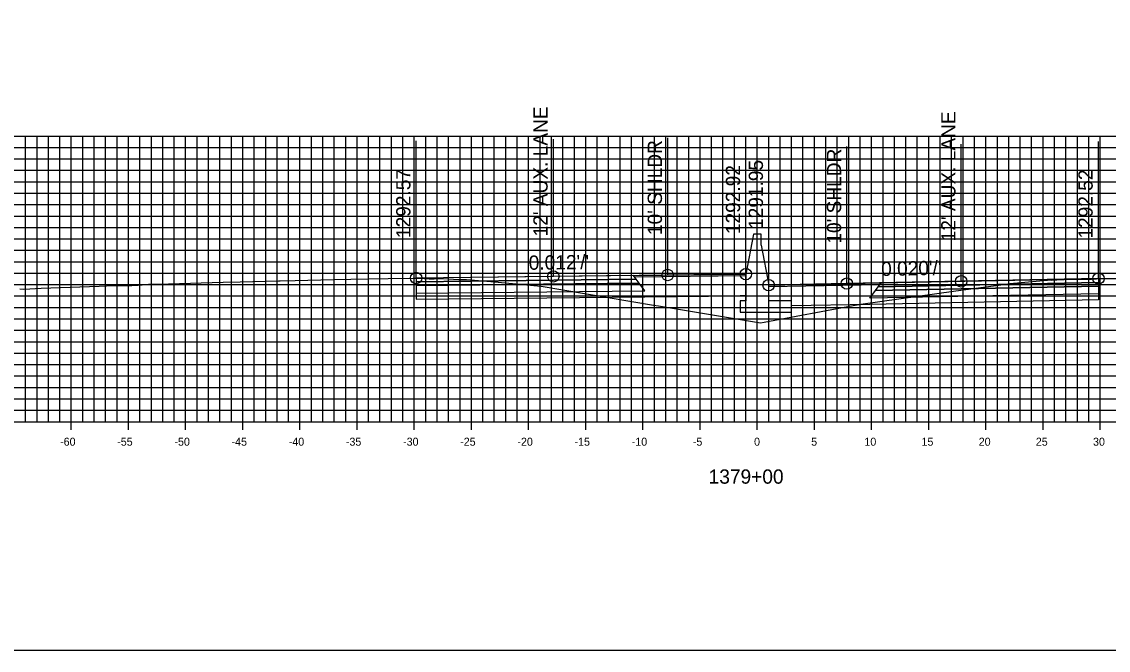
# Model space of a CAD drawing. Extents: x 674939 to 678919, y 750652 to 765176.
# Drawn here: x 678674.2 to 678769.2, y 755062.6 to 755117.6 of the extents above; entities that cross this region are included whole.
import ezdxf

# ---------------------------------------------------------------- set-up
doc = ezdxf.new("R2010")
doc.units = 0
for name, color, linetype in [('Level 10', 7, 'Continuous'), ('Level 17', 7, 'Continuous'), ('Level 18', 7, 'Continuous'), ('Level 19', 7, 'Continuous'), ('Level 20', 7, 'Continuous'), ('Level 22', 7, 'Continuous'), ('Level 23', 7, 'Continuous'), ('Level 4', 7, 'Continuous'), ('Level 8', 7, 'Continuous'), ('Level 9', 7, 'Continuous')]:
    doc.layers.add(name, color=color, linetype=linetype)

msp = doc.modelspace()

# ---------------------------------------------------------------- linework, layer by layer
at = {"layer": 'Level 10'}
msp.add_lwpolyline([(678674.042, 755094.176), (678674.332, 755094.156), (678674.913, 755094.185), (678675.9, 755094.228), (678680.981, 755094.416), (678682.242, 755094.463), (678683.839, 755094.479), (678684.388, 755094.492), (678685.071, 755094.555), (678685.277, 755094.571), (678685.32, 755094.575), (678685.387, 755094.58), (678687.032, 755094.629), (678691.823, 755094.767), (678693.303, 755094.803), (678696.642, 755094.871), (678696.807, 755094.878), (678698.114, 755094.919), (678701.455, 755094.984), (678704.511, 755095.042), (678706.253, 755095.078), (678708.433, 755095.11), (678708.698, 755095.122), (678708.723, 755095.124), (678708.733, 755095.124), (678708.952, 755095.107), (678709.824, 755095.066), (678710.261, 755095.06), (678710.988, 755095.069), (678712.441, 755095.007), (678712.934, 755094.987), (678712.972, 755094.992), (678713.088, 755095.009), (678715.225, 755094.813), (678719.621, 755094.414), (678729.443, 755092.761), (678729.89, 755092.688), (678732.508, 755092.249), (678738.826, 755091.191), (678739.145, 755091.247), (678746.926, 755092.731), (678747.79, 755092.861), (678755.694, 755093.961), (678760.289, 755094.601), (678760.626, 755094.632), (678764.228, 755094.97), (678764.277, 755094.957), (678764.307, 755094.946), (678764.746, 755094.956), (678766.015, 755095.011), (678766.893, 755095.028), (678767.781, 755095.037), (678768.199, 755095.065), (678768.372, 755095.075), (678768.588, 755095.088), (678768.707, 755095.095), (678769.952, 755095.095)], dxfattribs=at)
at = {"layer": 'Level 17'}
for points in [[(678738.203, 755098.967), (678737.533, 755095.467)], [(678738.863, 755097.998), (678738.863, 755098.967), (678738.203, 755098.967), (678738.203, 755098.967)], [(678738.863, 755097.998), (678739.533, 755094.498)], [(678737.533, 755095.467), (678737.533, 755093.123), (678737.033, 755093.123), (678737.033, 755092.123), (678741.533, 755092.123), (678741.533, 755093.123), (678739.533, 755093.123), (678739.533, 755094.498)]]:
    msp.add_lwpolyline(points, dxfattribs=at)
at = {"layer": 'Level 18'}
for points in [[(678737.533, 755095.467), (678730.698, 755095.385), (678720.698, 755095.266), (678708.698, 755095.122)], [(678768.372, 755095.075), (678756.372, 755094.835), (678746.372, 755094.635), (678739.533, 755094.498)]]:
    msp.add_lwpolyline(points, dxfattribs=at)
for points in [[(678708.698, 755095.122), (678708.698, 755094.792), (678727.948, 755095.014), (678727.698, 755095.349)], [(678727.698, 755095.349), (678737.533, 755095.467), (678737.537, 755095.309), (678727.817, 755095.189)], [(678749.253, 755094.535), (678739.533, 755094.341), (678739.533, 755094.498), (678749.372, 755094.695)], [(678768.372, 755095.075), (678768.372, 755094.745), (678749.122, 755094.36), (678749.372, 755094.695)]]:
    msp.add_lwpolyline(points, close=True, dxfattribs=at)
at = {"layer": 'Level 19'}
for points in [[(678708.698, 755094.792), (678708.698, 755094.462), (678728.198, 755094.679), (678727.948, 755095.014)], [(678708.698, 755094.462), (678708.698, 755093.802), (678728.698, 755094.009), (678728.198, 755094.679)], [(678768.372, 755094.415), (678768.372, 755093.755), (678748.372, 755093.355), (678748.872, 755094.025)], [(678768.372, 755094.745), (678768.372, 755094.415), (678748.872, 755094.025), (678749.122, 755094.36)]]:
    msp.add_lwpolyline(points, close=True, dxfattribs=at)
for points in [[(678708.698, 755093.802), (678708.698, 755093.262), (678728.698, 755093.469), (678737.033, 755093.556)], [(678737.534, 755093.561), (678737.033, 755093.556)], [(678768.372, 755093.755), (678768.372, 755093.215), (678748.372, 755092.815), (678741.533, 755092.678)]]:
    msp.add_lwpolyline(points, dxfattribs=at)
at = {"layer": 'Level 20'}
for p, q in [((678638.533, 755107.551), (678838.533, 755107.551)), ((678674.533, 755082.551), (678674.533, 755107.551)), ((678675.533, 755082.551), (678675.533, 755107.551)), ((678676.533, 755082.551), (678676.533, 755107.551)), ((678677.533, 755082.551), (678677.533, 755107.551)), ((678678.533, 755082.551), (678678.533, 755107.551)), ((678679.533, 755082.551), (678679.533, 755107.551)), ((678680.533, 755082.551), (678680.533, 755107.551)), ((678681.533, 755082.551), (678681.533, 755107.551)), ((678682.533, 755082.551), (678682.533, 755107.551)), ((678683.533, 755082.551), (678683.533, 755107.551)), ((678684.533, 755082.551), (678684.533, 755107.551)), ((678685.533, 755082.551), (678685.533, 755107.551)), ((678686.533, 755082.551), (678686.533, 755107.551)), ((678687.533, 755082.551), (678687.533, 755107.551)), ((678688.533, 755082.551), (678688.533, 755107.551)), ((678689.533, 755082.551), (678689.533, 755107.551)), ((678690.533, 755082.551), (678690.533, 755107.551)), ((678691.533, 755082.551), (678691.533, 755107.551)), ((678692.533, 755082.551), (678692.533, 755107.551)), ((678693.533, 755082.551), (678693.533, 755107.551)), ((678694.533, 755082.551), (678694.533, 755107.551)), ((678695.533, 755082.551), (678695.533, 755107.551)), ((678696.533, 755082.551), (678696.533, 755107.551)), ((678697.533, 755082.551), (678697.533, 755107.551)), ((678698.533, 755082.551), (678698.533, 755107.551)), ((678699.533, 755082.551), (678699.533, 755107.551)), ((678700.533, 755082.551), (678700.533, 755107.551)), ((678701.533, 755082.551), (678701.533, 755107.551)), ((678702.533, 755082.551), (678702.533, 755107.551)), ((678703.533, 755082.551), (678703.533, 755107.551)), ((678704.533, 755082.551), (678704.533, 755107.551)), ((678705.533, 755082.551), (678705.533, 755107.551)), ((678706.533, 755082.551), (678706.533, 755107.551)), ((678707.533, 755082.551), (678707.533, 755107.551)), ((678708.533, 755082.551), (678708.533, 755107.551)), ((678709.533, 755082.551), (678709.533, 755107.551)), ((678710.533, 755082.551), (678710.533, 755107.551)), ((678711.533, 755082.551), (678711.533, 755107.551)), ((678712.533, 755082.551), (678712.533, 755107.551)), ((678713.533, 755082.551), (678713.533, 755107.551)), ((678714.533, 755082.551), (678714.533, 755107.551)), ((678715.533, 755082.551), (678715.533, 755107.551)), ((678716.533, 755082.551), (678716.533, 755107.551)), ((678717.533, 755082.551), (678717.533, 755107.551)), ((678718.533, 755082.551), (678718.533, 755107.551)), ((678719.533, 755082.551), (678719.533, 755107.551)), ((678720.533, 755082.551), (678720.533, 755107.551)), ((678721.533, 755082.551), (678721.533, 755107.551)), ((678722.533, 755082.551), (678722.533, 755107.551)), ((678723.533, 755082.551), (678723.533, 755107.551)), ((678724.533, 755082.551), (678724.533, 755107.551)), ((678725.533, 755082.551), (678725.533, 755107.551)), ((678726.533, 755082.551), (678726.533, 755107.551)), ((678727.533, 755082.551), (678727.533, 755107.551)), ((678728.533, 755082.551), (678728.533, 755107.551)), ((678729.533, 755082.551), (678729.533, 755107.551)), ((678730.533, 755082.551), (678730.533, 755107.551)), ((678731.533, 755082.551), (678731.533, 755107.551)), ((678732.533, 755082.551), (678732.533, 755107.551)), ((678733.533, 755082.551), (678733.533, 755107.551)), ((678734.533, 755082.551), (678734.533, 755107.551)), ((678735.533, 755082.551), (678735.533, 755107.551)), ((678736.533, 755082.551), (678736.533, 755107.551)), ((678737.533, 755082.551), (678737.533, 755107.551)), ((678738.533, 755082.551), (678738.533, 755107.551)), ((678739.533, 755082.551), (678739.533, 755107.551)), ((678740.533, 755082.551), (678740.533, 755107.551)), ((678741.533, 755082.551), (678741.533, 755107.551)), ((678742.533, 755082.551), (678742.533, 755107.551)), ((678743.533, 755082.551), (678743.533, 755107.551)), ((678744.533, 755082.551), (678744.533, 755107.551)), ((678745.533, 755082.551), (678745.533, 755107.551)), ((678746.533, 755082.551), (678746.533, 755107.551)), ((678747.533, 755082.551), (678747.533, 755107.551)), ((678748.533, 755082.551), (678748.533, 755107.551)), ((678749.533, 755082.551), (678749.533, 755107.551)), ((678750.533, 755082.551), (678750.533, 755107.551)), ((678751.533, 755082.551), (678751.533, 755107.551)), ((678752.533, 755082.551), (678752.533, 755107.551)), ((678753.533, 755082.551), (678753.533, 755107.551)), ((678754.533, 755082.551), (678754.533, 755107.551)), ((678755.533, 755082.551), (678755.533, 755107.551)), ((678756.533, 755082.551), (678756.533, 755107.551)), ((678757.533, 755082.551), (678757.533, 755107.551)), ((678758.533, 755082.551), (678758.533, 755107.551)), ((678759.533, 755082.551), (678759.533, 755107.551)), ((678760.533, 755082.551), (678760.533, 755107.551)), ((678761.533, 755082.551), (678761.533, 755107.551)), ((678762.533, 755082.551), (678762.533, 755107.551)), ((678763.533, 755082.551), (678763.533, 755107.551)), ((678764.533, 755082.551), (678764.533, 755107.551)), ((678765.533, 755082.551), (678765.533, 755107.551)), ((678766.533, 755082.551), (678766.533, 755107.551)), ((678767.533, 755082.551), (678767.533, 755107.551)), ((678768.533, 755082.551), (678768.533, 755107.551)), ((678638.533, 755106.551), (678838.533, 755106.551)), ((678638.533, 755105.551), (678838.533, 755105.551)), ((678638.533, 755104.551), (678838.533, 755104.551)), ((678638.533, 755103.551), (678838.533, 755103.551)), ((678638.533, 755102.551), (678838.533, 755102.551)), ((678638.533, 755101.551), (678838.533, 755101.551)), ((678638.533, 755100.551), (678838.533, 755100.551)), ((678638.533, 755099.551), (678838.533, 755099.551)), ((678638.533, 755098.551), (678838.533, 755098.551)), ((678638.533, 755097.551), (678838.533, 755097.551)), ((678638.533, 755096.551), (678838.533, 755096.551)), ((678638.533, 755095.551), (678838.533, 755095.551)), ((678638.533, 755094.551), (678838.533, 755094.551)), ((678638.533, 755093.551), (678838.533, 755093.551)), ((678638.533, 755092.551), (678838.533, 755092.551)), ((678638.533, 755091.551), (678838.533, 755091.551)), ((678638.533, 755090.551), (678838.533, 755090.551)), ((678638.533, 755089.551), (678838.533, 755089.551)), ((678638.533, 755088.551), (678838.533, 755088.551)), ((678638.533, 755087.551), (678838.533, 755087.551)), ((678638.533, 755086.551), (678838.533, 755086.551)), ((678638.533, 755085.551), (678838.533, 755085.551)), ((678638.533, 755084.551), (678838.533, 755084.551)), ((678638.533, 755083.551), (678838.533, 755083.551)), ((678638.533, 755082.551), (678838.533, 755082.551))]:
    msp.add_line(p, q, dxfattribs=at)
at = {"layer": 'Level 23'}
for p, q in [((678708.698, 755095.122), (678708.698, 755107.122)), ((678720.698, 755095.266), (678720.698, 755107.266)), ((678730.698, 755095.385), (678730.698, 755107.385)), ((678737.533, 755095.467), (678737.533, 755107.467)), ((678756.372, 755094.835), (678756.372, 755106.835)), ((678768.372, 755095.075), (678768.372, 755107.075)), ((678739.533, 755094.498), (678739.533, 755106.498)), ((678746.372, 755094.635), (678746.372, 755106.635))]:
    msp.add_line(p, q, dxfattribs=at)
at = {"layer": 'Level 4'}
msp.add_lwpolyline([(678578.533, 755062.551), (678918.533, 755062.551), (678918.533, 755282.551), (678578.533, 755282.551)], close=True, dxfattribs=at)
for centre in [(678708.698, 755095.122), (678720.698, 755095.266), (678730.698, 755095.385), (678737.533, 755095.467), (678768.372, 755095.075), (678739.533, 755094.498), (678746.372, 755094.635), (678756.372, 755094.835)]:
    msp.add_circle(centre, 0.5, dxfattribs=at)
at = {"layer": 'Level 8'}
for p, q in [((678678.533, 755081.851), (678678.533, 755083.251)), ((678683.533, 755081.851), (678683.533, 755083.251)), ((678688.533, 755081.851), (678688.533, 755083.251)), ((678693.533, 755081.851), (678693.533, 755083.251)), ((678698.533, 755081.851), (678698.533, 755083.251)), ((678703.533, 755081.851), (678703.533, 755083.251)), ((678708.533, 755081.851), (678708.533, 755083.251)), ((678713.533, 755081.851), (678713.533, 755083.251)), ((678718.533, 755081.851), (678718.533, 755083.251)), ((678723.533, 755081.851), (678723.533, 755083.251)), ((678728.533, 755081.851), (678728.533, 755083.251)), ((678733.533, 755081.851), (678733.533, 755083.251)), ((678738.533, 755081.851), (678738.533, 755083.251)), ((678743.533, 755081.851), (678743.533, 755083.251)), ((678748.533, 755081.851), (678748.533, 755083.251)), ((678753.533, 755081.851), (678753.533, 755083.251)), ((678758.533, 755081.851), (678758.533, 755083.251)), ((678763.533, 755081.851), (678763.533, 755083.251)), ((678768.533, 755081.851), (678768.533, 755083.251)), ((678638.533, 755082.551), (678838.533, 755082.551))]:
    msp.add_line(p, q, dxfattribs=at)

# ---------------------------------------------------------------- texts
at = {"layer": 'Level 22'}
for s, rotation, p in [("0.012'/'", 0.685, (678718.546, 755095.84)), ("0.020'/'", 1.14576, (678749.379, 755095.295))]:
    msp.add_text(s, height=1.25, rotation=rotation, dxfattribs=at).set_placement(p)
at = {"layer": 'Level 23'}
for s, p in [("12' AUX. LANE", (678720.198, 755098.766)), ("12' AUX. LANE", (678755.872, 755098.335)), ("10' SHLDR", (678730.198, 755098.885)), ("10' SHLDR", (678745.872, 755098.135)), ('1292.92', (678737.033, 755098.967)), ('1291.95', (678739.033, 755099.417)), ('1292.57', (678708.198, 755098.622)), ('1292.52', (678767.872, 755098.575))]:
    msp.add_text(s, height=1.25, rotation=90, dxfattribs=at).set_placement(p)
at = {"layer": 'Level 9'}
for s, height, p in [('-60', 0.7, (678677.552, 755080.451)), ('-55', 0.7, (678682.546, 755080.451)), ('-50', 0.7, (678687.552, 755080.451)), ('-45', 0.7, (678692.546, 755080.451)), ('-40', 0.7, (678697.552, 755080.451)), ('-35', 0.7, (678702.546, 755080.451)), ('-30', 0.7, (678707.552, 755080.451)), ('-25', 0.7, (678712.546, 755080.451)), ('-20', 0.7, (678717.552, 755080.451)), ('-15', 0.7, (678722.546, 755080.451)), ('-10', 0.7, (678727.552, 755080.451)), ('-5', 0.7, (678732.896, 755080.451)), ('0', 0.7, (678738.252, 755080.451)), ('5', 0.7, (678743.246, 755080.451)), ('10', 0.7, (678747.902, 755080.451)), ('15', 0.7, (678752.896, 755080.451)), ('20', 0.7, (678757.902, 755080.451)), ('25', 0.7, (678762.896, 755080.451)), ('30', 0.7, (678767.902, 755080.451)), ('1379+00', 1.25, (678734.281, 755077.126))]:
    msp.add_text(s, height=height, dxfattribs=at).set_placement(p)

doc.saveas('drawing.dxf')
